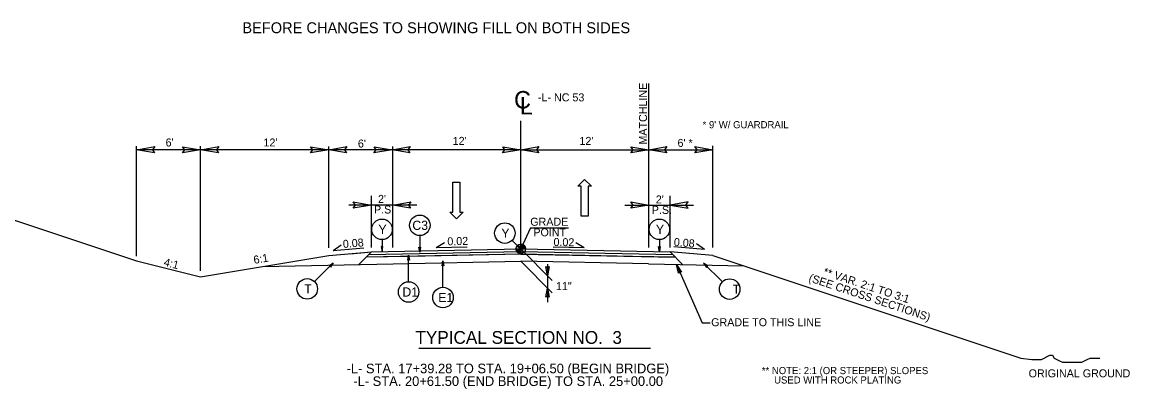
# Model space of a CAD drawing. Extents: x 1548135 to 1549339, y 868664 to 869085.
# Drawn here: x 1548427.5 to 1548531.3, y 868892.9 to 868927.3 of the extents above; entities that cross this region are included whole.
import ezdxf

# ---------------------------------------------------------------- set-up
doc = ezdxf.new("R2010")
doc.units = 0
for name, color, linetype in [('P_RDY_TC_Pvmt_Asphalt_Base_Course', 7, 'Continuous'), ('Prop Dimension', 7, 'Continuous'), ('Prop Dimension Text', 7, 'Continuous'), ('Prop Terminator CELL', 7, 'Continuous'), ('Sheet_Data_Field_CELL', 7, 'Continuous'), ('Sheet_Plan', 7, 'Continuous'), ('Sheet_Title_Block_Text', 7, 'Continuous'), ('Typical Curb CELL', 7, 'Continuous'), ('Typical Grade Point Symbol CELL', 7, 'Continuous'), ('Typical Hinge Slope Arterial CELL', 7, 'Continuous'), ('Typical Hinge Slope Interstate CELL', 7, 'Continuous'), ('Typical Pavement Slope CELL', 7, 'Continuous'), ('Typical Pavement Slope Information CELL', 7, 'Continuous'), ('Typical Shoulder Slope CELL', 7, 'Continuous'), ('Typical Shoulder Slope Information CELL', 7, 'Continuous'), ('Typical Terminator CELL', 7, 'Continuous'), ('Typical Text Centerline CELL', 7, 'Continuous'), ('Typical Text General CELL', 7, 'Continuous'), ('Typical Text Grade Point CELL', 7, 'Continuous'), ('z - Construction', 7, 'Continuous')]:
    doc.layers.add(name, color=color, linetype=linetype)

msp = doc.modelspace()

# ---------------------------------------------------------------- linework, layer by layer
at = {"layer": 'P_RDY_TC_Pvmt_Asphalt_Base_Course'}
for points in [[(1548439.93, 868915.03), (1548438.24, 868915.33), (1548439.94, 868915.63), (1548439.72, 868915.33)], [(1548442.55, 868915.62), (1548444.24, 868915.33), (1548442.54, 868915.03), (1548442.76, 868915.33)], [(1548445.93, 868915.03), (1548444.24, 868915.33), (1548445.94, 868915.63), (1548445.72, 868915.33)], [(1548454.55, 868915.62), (1548456.24, 868915.33), (1548454.54, 868915.03), (1548454.76, 868915.33)], [(1548457.92, 868915.03), (1548456.24, 868915.33), (1548457.93, 868915.63), (1548457.72, 868915.33)], [(1548460.49, 868915.62), (1548462.18, 868915.33), (1548460.48, 868915.03), (1548460.7, 868915.33)], [(1548463.86, 868915.03), (1548462.18, 868915.33), (1548463.87, 868915.63), (1548463.66, 868915.33)], [(1548472.55, 868915.62), (1548474.24, 868915.33), (1548472.54, 868915.03), (1548472.76, 868915.33)], [(1548475.92, 868915.03), (1548474.24, 868915.33), (1548475.93, 868915.63), (1548475.72, 868915.33)], [(1548484.55, 868915.62), (1548486.24, 868915.33), (1548484.54, 868915.03), (1548484.76, 868915.33)], [(1548487.92, 868915.03), (1548486.24, 868915.33), (1548487.93, 868915.63), (1548487.72, 868915.33)], [(1548490.56, 868915.63), (1548492.25, 868915.34), (1548490.55, 868915.04), (1548490.77, 868915.34)], [(1548458.55, 868910.44), (1548460.24, 868910.15), (1548458.54, 868909.85), (1548458.76, 868910.15)], [(1548463.92, 868909.86), (1548462.24, 868910.15), (1548463.93, 868910.45), (1548463.72, 868910.15)], [(1548484.55, 868910.44), (1548486.24, 868910.15), (1548484.54, 868909.85), (1548484.76, 868910.15)], [(1548489.92, 868910.44), (1548488.24, 868910.15), (1548489.93, 868909.85), (1548489.72, 868910.15)]]:
    msp.add_lwpolyline(points, close=True, dxfattribs=at)
at = {"layer": 'Prop Dimension'}
msp.add_lwpolyline([(1548521.1, 868895.81), (1548522.13, 868895.68), (1548522.39, 868895.68), (1548522.78, 868895.68), (1548523.04, 868895.68), (1548523.3, 868895.81), (1548523.56, 868895.94), (1548523.82, 868896.07), (1548524.08, 868896.07), (1548524.21, 868895.81), (1548524.47, 868895.68), (1548524.73, 868895.55), (1548524.99, 868895.42), (1548525.25, 868895.42), (1548525.51, 868895.42), (1548525.77, 868895.42), (1548526.02, 868895.42), (1548526.28, 868895.42), (1548526.54, 868895.42), (1548526.8, 868895.42), (1548527.06, 868895.55), (1548527.32, 868895.68), (1548527.58, 868895.81), (1548527.97, 868895.81), (1548528.23, 868895.81), (1548528.49, 868895.81)], dxfattribs=at)
at = {"layer": 'Prop Dimension Text'}
for p, q in [((1548459.99, 868905.5), (1548474.24, 868905.79)), ((1548474.24, 868905.79), (1548488.49, 868905.5))]:
    msp.add_line(p, q, dxfattribs=at)
at = {"layer": 'Prop Terminator CELL'}
msp.add_lwpolyline([(1548460.24, 868905.76), (1548474.24, 868906.04), (1548488.24, 868905.76), (1548488.74, 868905.25), (1548484.7, 868905.32), (1548483.27, 868905.36), (1548481.73, 868905.39), (1548474.24, 868905.54), (1548474.24, 868905.54), (1548463.77, 868905.32), (1548459.74, 868905.25)], close=True, dxfattribs=at)
at = {"layer": 'Sheet_Data_Field_CELL'}
for p, q in [((1548409.39, 868914.54), (1548438.24, 868904.93)), ((1548444.24, 868903.43), (1548456.24, 868905.43)), ((1548492.25, 868905.42), (1548521.1, 868895.81)), ((1548438.24, 868904.93), (1548444.24, 868903.43))]:
    msp.add_line(p, q, dxfattribs=at)
at = {"layer": 'Sheet_Plan'}
for p, q in [((1548456.24, 868905.43), (1548460.24, 868905.76)), ((1548492.25, 868905.42), (1548488.24, 868905.76))]:
    msp.add_line(p, q, dxfattribs=at)
at = {"layer": 'Typical Curb CELL'}
for p, q in [((1548474.24, 868906.04), (1548474.24, 868906.49)), ((1548473.79, 868906.04), (1548474.24, 868906.04)), ((1548474.68, 868906.04), (1548474.24, 868906.04)), ((1548474.24, 868905.59), (1548474.24, 868906.04)), ((1548474.24, 868906.04), (1548474.24, 868905.59))]:
    msp.add_line(p, q, dxfattribs=at)
for points in [[(1548474.24, 868906.49), (1548474.24, 868906.49), (1548474.24, 868906.04)], [(1548474.25, 868906.49), (1548474.25, 868906.04)], [(1548474.26, 868906.49), (1548474.26, 868906.04)], [(1548474.27, 868906.49), (1548474.27, 868906.04)], [(1548474.28, 868906.48), (1548474.28, 868906.04)], [(1548474.29, 868906.48), (1548474.29, 868906.04)], [(1548474.29, 868906.48), (1548474.29, 868906.04)], [(1548474.3, 868906.48), (1548474.3, 868906.04)], [(1548474.31, 868906.48), (1548474.31, 868906.04)], [(1548474.32, 868906.48), (1548474.32, 868906.04)], [(1548474.33, 868906.48), (1548474.33, 868906.04)], [(1548474.34, 868906.47), (1548474.34, 868906.04)], [(1548474.35, 868906.47), (1548474.35, 868906.04)], [(1548474.36, 868906.47), (1548474.36, 868906.04)], [(1548474.37, 868906.47), (1548474.37, 868906.04)], [(1548474.37, 868906.46), (1548474.37, 868906.04)], [(1548474.38, 868906.46), (1548474.38, 868906.04)], [(1548474.39, 868906.46), (1548474.39, 868906.04)], [(1548474.4, 868906.45), (1548474.4, 868906.04)], [(1548474.41, 868906.45), (1548474.41, 868906.04)], [(1548474.42, 868906.45), (1548474.42, 868906.04)], [(1548474.43, 868906.44), (1548474.43, 868906.04)], [(1548474.44, 868906.44), (1548474.44, 868906.04)], [(1548474.45, 868906.43), (1548474.45, 868906.04)], [(1548474.46, 868906.43), (1548474.46, 868906.04)], [(1548474.46, 868906.42), (1548474.46, 868906.04)], [(1548474.47, 868906.42), (1548474.47, 868906.04)], [(1548474.48, 868906.41), (1548474.48, 868906.04)], [(1548474.49, 868906.41), (1548474.49, 868906.04)], [(1548474.5, 868906.4), (1548474.5, 868906.04)], [(1548474.51, 868906.39), (1548474.51, 868906.04)], [(1548474.52, 868906.39), (1548474.52, 868906.04)], [(1548474.53, 868906.38), (1548474.53, 868906.04)], [(1548474.54, 868906.37), (1548474.54, 868906.04)], [(1548474.54, 868906.36), (1548474.54, 868906.04)], [(1548474.55, 868906.35), (1548474.55, 868906.04)], [(1548474.56, 868906.35), (1548474.56, 868906.04)], [(1548474.57, 868906.34), (1548474.57, 868906.04)], [(1548474.58, 868906.32), (1548474.58, 868906.04)], [(1548474.59, 868906.31), (1548474.59, 868906.04)], [(1548474.6, 868906.3), (1548474.6, 868906.04)], [(1548474.61, 868906.29), (1548474.61, 868906.04)], [(1548474.62, 868906.27), (1548474.62, 868906.04)], [(1548474.63, 868906.26), (1548474.63, 868906.04)], [(1548474.63, 868906.24), (1548474.63, 868906.04)], [(1548474.64, 868906.22), (1548474.64, 868906.04)], [(1548474.65, 868906.2), (1548474.65, 868906.04)], [(1548473.79, 868906.04), (1548473.79, 868905.99)], [(1548473.8, 868906.04), (1548473.8, 868905.94)], [(1548473.81, 868906.04), (1548473.81, 868905.91)], [(1548473.82, 868906.04), (1548473.82, 868905.88)], [(1548473.83, 868906.04), (1548473.83, 868905.86)], [(1548473.84, 868906.04), (1548473.84, 868905.84)], [(1548473.84, 868906.04), (1548473.84, 868905.82)], [(1548473.85, 868906.04), (1548473.85, 868905.81)], [(1548473.86, 868906.04), (1548473.86, 868905.79)], [(1548473.87, 868906.04), (1548473.87, 868905.78)], [(1548473.88, 868906.04), (1548473.88, 868905.77)], [(1548473.89, 868906.04), (1548473.89, 868905.76)], [(1548473.9, 868906.04), (1548473.9, 868905.75)], [(1548473.91, 868906.04), (1548473.91, 868905.74)], [(1548473.92, 868906.04), (1548473.92, 868905.73)], [(1548473.92, 868906.04), (1548473.92, 868905.72)], [(1548473.93, 868906.04), (1548473.93, 868905.71)], [(1548473.94, 868906.04), (1548473.94, 868905.7)], [(1548473.95, 868906.04), (1548473.95, 868905.69)], [(1548473.96, 868906.04), (1548473.96, 868905.69)], [(1548473.97, 868906.04), (1548473.97, 868905.68)], [(1548473.98, 868906.04), (1548473.98, 868905.67)], [(1548473.99, 868906.04), (1548473.99, 868905.67)], [(1548474, 868906.04), (1548474, 868905.66)], [(1548474.01, 868906.04), (1548474.01, 868905.66)], [(1548474.01, 868906.04), (1548474.01, 868905.65)], [(1548474.02, 868906.04), (1548474.02, 868905.65)], [(1548474.03, 868906.04), (1548474.03, 868905.64)], [(1548474.04, 868906.04), (1548474.04, 868905.64)], [(1548474.05, 868906.04), (1548474.05, 868905.63)], [(1548474.06, 868906.04), (1548474.06, 868905.63)], [(1548474.07, 868906.04), (1548474.07, 868905.62)], [(1548474.08, 868906.04), (1548474.08, 868905.62)], [(1548474.09, 868906.04), (1548474.09, 868905.62)], [(1548474.1, 868906.04), (1548474.1, 868905.61)], [(1548474.1, 868906.04), (1548474.1, 868905.61)], [(1548474.11, 868906.04), (1548474.11, 868905.61)], [(1548474.12, 868906.04), (1548474.12, 868905.61)], [(1548474.13, 868906.04), (1548474.13, 868905.6)], [(1548474.14, 868906.04), (1548474.14, 868905.6)], [(1548474.15, 868906.04), (1548474.15, 868905.6)], [(1548474.16, 868906.04), (1548474.16, 868905.6)], [(1548474.17, 868906.04), (1548474.17, 868905.6)], [(1548474.18, 868906.04), (1548474.18, 868905.6)], [(1548474.18, 868906.04), (1548474.18, 868905.59)], [(1548474.19, 868906.04), (1548474.19, 868905.59)], [(1548474.2, 868906.04), (1548474.2, 868905.59)], [(1548474.21, 868906.04), (1548474.21, 868905.59)], [(1548474.22, 868906.04), (1548474.22, 868905.59)], [(1548474.23, 868906.04), (1548474.23, 868905.59), (1548474.23, 868905.59)], [(1548474.66, 868906.18), (1548474.66, 868906.04)], [(1548474.67, 868906.15), (1548474.67, 868906.04)], [(1548474.68, 868906.1), (1548474.68, 868906.04)]]:
    msp.add_lwpolyline(points, dxfattribs=at)
msp.add_circle((1548474.24, 868906.04), 0.448, dxfattribs=at)
for start, end in [(359.9905, 89.9905), (179.9905, 269.9905)]:
    msp.add_arc((1548474.24, 868906.04), 0.448, start, end, dxfattribs=at)
at = {"layer": 'Typical Grade Point Symbol CELL'}
for p, q in [((1548486.24, 868906.16), (1548486.24, 868921.56)), ((1548474.24, 868906.04), (1548474.24, 868918.03)), ((1548438.24, 868905.36), (1548438.24, 868915.67)), ((1548444.24, 868903.97), (1548444.24, 868915.67)), ((1548456.24, 868906.14), (1548456.24, 868915.65)), ((1548462.24, 868906.16), (1548462.24, 868915.65)), ((1548486.24, 868906.16), (1548486.24, 868915.67)), ((1548492.25, 868906.18), (1548492.25, 868915.69)), ((1548474.24, 868915.33), (1548438.24, 868915.33)), ((1548461.24, 868915.33), (1548459.24, 868915.33)), ((1548474.24, 868915.33), (1548492.25, 868915.33)), ((1548487.24, 868915.33), (1548489.24, 868915.33)), ((1548460.24, 868906.16), (1548460.24, 868911)), ((1548488.24, 868906.16), (1548488.24, 868911)), ((1548464.49, 868910.15), (1548458.13, 868910.15)), ((1548483.99, 868910.15), (1548490.42, 868910.15))]:
    msp.add_line(p, q, dxfattribs=at)
at = {"layer": 'Typical Hinge Slope Arterial CELL'}
msp.add_line((1548475.16, 868908.03), (1548478.72, 868908.03), dxfattribs=at)
at = {"layer": 'Typical Hinge Slope Interstate CELL'}
for p, q in [((1548464.78, 868907.29), (1548464.78, 868905.73)), ((1548461.24, 868906.91), (1548461.24, 868905.78)), ((1548473.43, 868906.84), (1548474.24, 868906.04)), ((1548487.23, 868906.91), (1548487.23, 868905.78)), ((1548458.24, 868905.59), (1548460.24, 868905.76)), ((1548460.24, 868905.76), (1548459.07, 868904.58)), ((1548463.73, 868902.96), (1548463.73, 868905.45)), ((1548477.19, 868903.09), (1548474.24, 868906.04)), ((1548454.91, 868902.97), (1548456.67, 868904.73)), ((1548462.27, 868904.64), (1548474.24, 868904.88)), ((1548466.95, 868902.45), (1548466.95, 868904.93)), ((1548486.21, 868904.64), (1548474.24, 868904.88)), ((1548477.19, 868901.93), (1548474.24, 868904.88)), ((1548476.74, 868904.61), (1548476.74, 868901.06)), ((1548493.13, 868902.95), (1548491.37, 868904.7))]:
    msp.add_line(p, q, dxfattribs=at)
for points in [[(1548461.16, 868906.25), (1548461.24, 868905.78), (1548461.32, 868906.25), (1548461.24, 868906.19)], [(1548464.86, 868906.2), (1548464.78, 868905.73), (1548464.69, 868906.2), (1548464.78, 868906.14)], [(1548473.96, 868906.43), (1548474.24, 868906.04), (1548473.84, 868906.31), (1548473.95, 868906.33)], [(1548487.31, 868906.25), (1548487.23, 868905.78), (1548487.15, 868906.25), (1548487.23, 868906.19)], [(1548463.65, 868904.98), (1548463.73, 868905.45), (1548463.81, 868904.98), (1548463.73, 868905.04)], [(1548456.28, 868904.45), (1548456.67, 868904.73), (1548456.4, 868904.33), (1548456.38, 868904.44)], [(1548466.87, 868904.46), (1548466.95, 868904.93), (1548467.04, 868904.46), (1548466.95, 868904.52)], [(1548476.89, 868904.38), (1548476.74, 868903.53), (1548476.59, 868904.38), (1548476.74, 868904.27)], [(1548489.03, 868903.76), (1548488.82, 868904.59), (1548489.3, 868903.87), (1548489.12, 868903.91)], [(1548491.76, 868904.43), (1548491.37, 868904.7), (1548491.65, 868904.31), (1548491.66, 868904.41)], [(1548476.6, 868901.53), (1548476.74, 868902.37), (1548476.89, 868901.53), (1548476.74, 868901.63)]]:
    msp.add_lwpolyline(points, close=True, dxfattribs=at)
msp.add_lwpolyline([(1548488.82, 868904.59), (1548491.25, 868899.12), (1548492, 868899.12)], dxfattribs=at)
for centre in [(1548461.24, 868907.87), (1548464.78, 868908.25), (1548472.75, 868907.52), (1548487.23, 868907.87), (1548454.23, 868902.29), (1548493.81, 868902.27), (1548463.73, 868902), (1548466.95, 868901.48)]:
    msp.add_circle(centre, 0.962, dxfattribs=at)
at = {"layer": 'Typical Pavement Slope CELL'}
msp.add_line((1548460.24, 868905.76), (1548474.24, 868906.04), dxfattribs=at)
at = {"layer": 'Typical Pavement Slope Information CELL'}
for p, q in [((1548456.67, 868905.89), (1548457.42, 868906.41)), ((1548466.32, 868906.17), (1548467.1, 868906.65)), ((1548466.32, 868906.17), (1548469.21, 868906.23)), ((1548480.17, 868906.13), (1548479.39, 868906.6)), ((1548491.47, 868905.99), (1548488.59, 868906.23)), ((1548491.47, 868905.99), (1548490.72, 868906.51)), ((1548456.67, 868905.89), (1548459.55, 868906.13)), ((1548480.17, 868906.13), (1548477.28, 868906.19))]:
    msp.add_line(p, q, dxfattribs=at)
at = {"layer": 'Typical Shoulder Slope CELL'}
msp.add_line((1548475.16, 868908.03), (1548474.24, 868906.04), dxfattribs=at)
at = {"layer": 'Typical Shoulder Slope Information CELL'}
for p, q in [((1548479.6, 868911.91), (1548480.22, 868912.54)), ((1548480.22, 868912.54), (1548480.86, 868911.91)), ((1548467.88, 868909.49), (1548467.88, 868912.29)), ((1548467.88, 868912.29), (1548468.54, 868912.29)), ((1548468.54, 868912.29), (1548468.54, 868909.49)), ((1548479.9, 868911.91), (1548479.6, 868911.91)), ((1548479.9, 868909.11), (1548479.9, 868911.91)), ((1548480.86, 868911.91), (1548480.56, 868911.91)), ((1548480.56, 868911.91), (1548480.56, 868909.11)), ((1548468.22, 868908.86), (1548467.58, 868909.49)), ((1548467.58, 868909.49), (1548467.88, 868909.49)), ((1548468.84, 868909.49), (1548468.22, 868908.86)), ((1548468.54, 868909.49), (1548468.84, 868909.49)), ((1548480.56, 868909.11), (1548479.9, 868909.11))]:
    msp.add_line(p, q, dxfattribs=at)
at = {"layer": 'Typical Terminator CELL'}
msp.add_line((1548464.68, 868896.74), (1548486.41, 868896.74), dxfattribs=at)
at = {"layer": 'Typical Text Grade Point CELL'}
for p, q in [((1548474.24, 868905.54), (1548459.74, 868905.25)), ((1548474.24, 868906.04), (1548488.24, 868905.76)), ((1548474.24, 868905.54), (1548488.74, 868905.25)), ((1548488.24, 868905.76), (1548489.4, 868904.58)), ((1548450.05, 868904.4), (1548462.27, 868904.64)), ((1548486.21, 868904.64), (1548495.14, 868904.46))]:
    msp.add_line(p, q, dxfattribs=at)

# ---------------------------------------------------------------- texts
at = {"layer": 'Sheet_Data_Field_CELL'}
for s, rotation, p in [('6:1', 9.4623, (1548449.26, 868904.63)), ('4:1', 345.9638, (1548440.74, 868904.47)), ('** VAR. 2:1 TO 3:1', 341.565, (1548502.53, 868903.6)), ('(SEE CROSS SECTIONS)', 341.565, (1548501.16, 868903.02))]:
    msp.add_text(s, height=0.75, rotation=rotation, dxfattribs=at).set_placement(p)
msp.add_text('ORIGINAL GROUND', height=0.75, dxfattribs=at).set_placement((1548521.83, 868894))
at = {"layer": 'Sheet_Title_Block_Text'}
msp.add_text('C', height=1.64, dxfattribs=at).set_placement((1548473.61, 868919.2))
msp.add_text('L', height=1.64, rotation=359.9469, dxfattribs=at).set_placement((1548474.15, 868918.64))
at = {"layer": 'Typical Hinge Slope Arterial CELL'}
msp.add_text('TYPICAL SECTION NO.  3', height=1.2, dxfattribs=at).set_placement((1548464.37, 868897.14))
at = {"layer": 'Typical Hinge Slope Interstate CELL'}
for s, height, p in [('BEFORE CHANGES TO SHOWING FILL ON BOTH SIDES', 1.0232, (1548448.15, 868926.26)), ('-L- NC 53', 0.75, (1548475.85, 868919.87)), ('Y', 0.861, (1548460.9, 868907.44)), ('C3', 0.861, (1548464.08, 868907.82)), ('Y', 0.861, (1548486.9, 868907.44)), ('Y', 0.861, (1548472.42, 868907.09)), ('T', 0.861, (1548453.95, 868901.86)), ('D1', 0.861, (1548463.15, 868901.57)), ('11"', 0.75, (1548477.54, 868902.18)), ('T', 0.861, (1548494.09, 868901.84)), ('E1', 0.861, (1548466.5, 868901.05)), ('GRADE TO THIS LINE', 0.75, (1548492.08, 868898.79))]:
    msp.add_text(s, height=height, dxfattribs=at).set_placement(p)
msp.add_text('MATCHLINE', height=0.75, rotation=90, dxfattribs=at).set_placement((1548486.07, 868915.82))
at = {"layer": 'Typical Pavement Slope Information CELL'}
for rotation, p in [(1.4551, (1548467.37, 868906.37)), (358.8544, (1548477.3, 868906.32))]:
    msp.add_text('0.02', height=0.75, rotation=rotation, dxfattribs=at).set_placement(p)
at = {"layer": 'Typical Shoulder Slope CELL'}
for s, p in [("6'", (1548440.96, 868915.64)), ("12'", (1548450.13, 868915.64)), ("6'", (1548458.98, 868915.54)), ("12'", (1548467.86, 868915.79)), ("12'", (1548479.74, 868915.79)), ("6' *", (1548488.93, 868915.6)), ('GRADE', (1548475.13, 868908.21)), ('POINT', (1548475.42, 868907.22))]:
    msp.add_text(s, height=0.75, dxfattribs=at).set_placement(p)
at = {"layer": 'Typical Text Centerline CELL'}
for s, p in [("2'", (1548460.86, 868910.35)), ("2'", (1548486.89, 868910.3)), ('P.S.', (1548460.49, 868909.36)), ('P.S.', (1548486.52, 868909.32))]:
    msp.add_text(s, height=0.75, dxfattribs=at).set_placement(p)
at = {"layer": 'Typical Text General CELL'}
for s, height, p in [("* 9' W/ GUARDRAIL", 0.6682, (1548491.28, 868917.35)), ('-L- STA. 17+39.28 TO STA. 19+06.50 (BEGIN BRIDGE)', 0.9039, (1548457.92, 868894.38)), ('** NOTE: 2:1 (OR STEEPER) SLOPES ', 0.6682, (1548496.83, 868894.3)), ('-L- STA. 20+61.50 (END BRIDGE) TO STA. 25+00.00', 0.9039, (1548458.55, 868893.19)), ('USED WITH ROCK PLATING', 0.6682, (1548497.98, 868893.42))]:
    msp.add_text(s, height=height, dxfattribs=at).set_placement(p)
at = {"layer": 'z - Construction'}
for rotation, p in [(4.7615, (1548457.6, 868906.12)), (355.2385, (1548488.56, 868906.33))]:
    msp.add_text('0.08', height=0.75, rotation=rotation, dxfattribs=at).set_placement(p)

doc.saveas('drawing.dxf')
